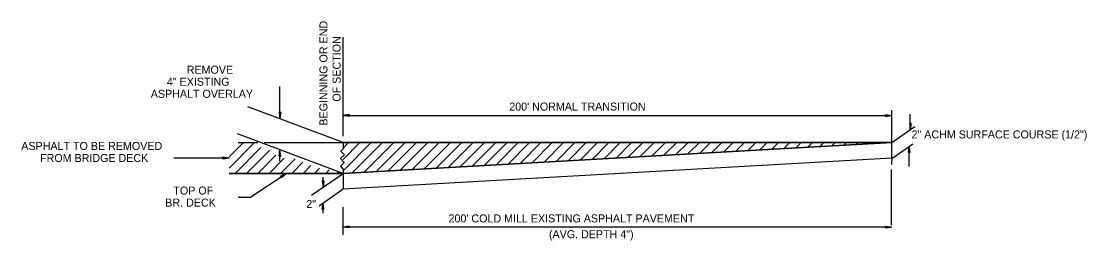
# Model space of a CAD drawing. Extents: x 1929624 to 1936506, y 596315 to 605721.
# Drawn here: x 1935707 to 1936506, y 602708 to 602872 of the extents above; entities that cross this region are included whole.
import ezdxf

# ---------------------------------------------------------------- set-up
doc = ezdxf.new("R2010")
doc.units = 0
doc.layers.add('Default', color=7, linetype='Continuous')
doc.layers.add('R_Border', color=7, linetype='Continuous')

msp = doc.modelspace()

# ---------------------------------------------------------------- linework, layer by layer
at = {"layer": 'Default'}
for p, q in [((1935948.07, 602786.61), (1935948.07, 602860.53)), ((1935900.69, 602799.72), (1935900.69, 602823.71)), ((1935948.07, 602781.78), (1935876.52, 602808.5)), ((1935900.02, 602804.17), (1935900.69, 602799.72)), ((1935900.02, 602804.17), (1935900.69, 602800.38)), ((1935901.35, 602804.17), (1935900.02, 602804.17)), ((1935900.25, 602804.17), (1935900.69, 602801.28)), ((1935900.25, 602804.17), (1935900.69, 602801.93)), ((1935900.47, 602804.17), (1935900.69, 602802.83)), ((1935900.47, 602804.17), (1935900.69, 602803.49)), ((1935901.35, 602804.17), (1935900.69, 602799.72)), ((1935900.9, 602804.17), (1935900.69, 602802.83)), ((1935901.14, 602804.17), (1935900.69, 602801.28)), ((1935901.14, 602804.17), (1935900.69, 602800.38)), ((1935900.9, 602804.17), (1935900.69, 602801.93)), ((1935900.69, 602804.17), (1935900.69, 602803.49)), ((1935952.74, 602802.67), (1935948.07, 602802)), ((1935948.07, 602802), (1936359.63, 602802)), ((1935952.74, 602801.34), (1935948.07, 602802)), ((1935952.74, 602802.45), (1935948.75, 602802)), ((1935952.74, 602801.34), (1935948.75, 602802)), ((1935952.74, 602802.45), (1935949.64, 602802)), ((1935952.74, 602801.56), (1935949.64, 602802)), ((1935952.74, 602802.23), (1935950.53, 602802)), ((1935952.74, 602801.56), (1935950.53, 602802)), ((1935952.74, 602802.23), (1935951.19, 602802)), ((1935952.74, 602801.79), (1935951.19, 602802)), ((1935952.74, 602802), (1935952.08, 602802)), ((1935952.74, 602801.79), (1935952.08, 602802)), ((1935952.74, 602801.34), (1935952.74, 602802.67)), ((1936354.96, 602802.67), (1936359.63, 602802)), ((1936354.96, 602802.67), (1936354.96, 602801.34)), ((1936354.96, 602802.45), (1936358.08, 602802)), ((1936354.96, 602802.45), (1936358.72, 602802)), ((1936354.96, 602802.23), (1936356.51, 602802)), ((1936354.96, 602802.23), (1936357.19, 602802)), ((1936354.96, 602801.34), (1936359.63, 602802)), ((1936354.96, 602801.79), (1936356.51, 602802)), ((1936354.96, 602801.56), (1936358.08, 602802)), ((1936354.96, 602801.34), (1936358.72, 602802)), ((1936354.96, 602801.56), (1936357.19, 602802)), ((1936354.96, 602801.79), (1936355.63, 602802)), ((1936354.96, 602802), (1936355.63, 602802)), ((1936359.63, 602781.78), (1936359.63, 602805.99)), ((1936373.39, 602791.32), (1936373.39, 602803.09)), ((1936359.63, 602781.78), (1936376.95, 602793.77)), ((1936372.73, 602795.98), (1936373.39, 602791.32)), ((1936374.06, 602795.98), (1936372.73, 602795.98)), ((1936372.96, 602795.98), (1936373.39, 602792.88)), ((1936372.96, 602795.98), (1936373.39, 602792.21)), ((1936373.17, 602795.98), (1936373.39, 602794.44)), ((1936373.17, 602795.98), (1936373.39, 602793.77)), ((1936374.06, 602795.98), (1936373.39, 602791.32)), ((1936373.61, 602795.98), (1936373.39, 602794.44)), ((1936373.85, 602795.98), (1936373.39, 602792.88)), ((1936374.06, 602795.98), (1936373.39, 602792.21)), ((1936373.85, 602795.98), (1936373.39, 602793.77)), ((1936373.39, 602795.98), (1936373.39, 602795.32)), ((1936373.61, 602795.98), (1936373.39, 602795.32)), ((1935948.01, 602758.7), (1935868.93, 602788.16)), ((1935862.62, 602762.68), (1935881.73, 602781.78)), ((1935862.62, 602771.16), (1935873.25, 602781.78)), ((1935867.14, 602758.7), (1935886.47, 602778.03)), ((1935869.44, 602781.78), (1935884.08, 602781.78)), ((1935888.85, 602781.78), (1935898.31, 602781.78)), ((1935898.31, 602781.78), (1936359.63, 602781.78)), ((1935948.07, 602777.66), (1935952.19, 602781.78)), ((1935948.08, 602769.19), (1935960.68, 602781.78)), ((1935948.09, 602760.71), (1935969.17, 602781.78)), ((1935954.96, 602759.09), (1935977.65, 602781.78)), ((1935963.95, 602759.6), (1935986.14, 602781.78)), ((1935972.94, 602760.1), (1935994.62, 602781.78)), ((1935981.93, 602760.61), (1936003.11, 602781.78)), ((1935990.92, 602761.11), (1936011.59, 602781.78)), ((1935999.91, 602761.61), (1936020.08, 602781.78)), ((1936008.9, 602762.12), (1936028.56, 602781.78)), ((1936017.89, 602762.62), (1936037.05, 602781.78)), ((1936026.87, 602763.13), (1936045.53, 602781.78)), ((1936035.86, 602763.63), (1936054.02, 602781.78)), ((1936044.85, 602764.13), (1936062.5, 602781.78)), ((1936053.84, 602764.64), (1936070.99, 602781.78)), ((1936062.83, 602765.14), (1936079.47, 602781.78)), ((1936071.82, 602765.65), (1936087.96, 602781.78)), ((1936080.81, 602766.15), (1936096.44, 602781.78)), ((1936089.8, 602766.65), (1936104.93, 602781.78)), ((1936098.79, 602767.16), (1936113.41, 602781.78)), ((1936107.78, 602767.66), (1936121.9, 602781.78)), ((1936116.77, 602768.17), (1936130.39, 602781.78)), ((1936125.76, 602768.67), (1936138.87, 602781.78)), ((1936134.75, 602769.17), (1936147.36, 602781.78)), ((1936143.74, 602769.68), (1936155.84, 602781.78)), ((1936152.73, 602770.18), (1936164.33, 602781.78)), ((1936161.71, 602770.69), (1936172.81, 602781.78)), ((1936170.7, 602771.19), (1936181.3, 602781.78)), ((1936179.69, 602771.69), (1936189.78, 602781.78)), ((1936188.68, 602772.2), (1936198.27, 602781.78)), ((1936197.67, 602772.7), (1936206.75, 602781.78)), ((1936206.66, 602773.21), (1936215.24, 602781.78)), ((1936215.65, 602773.71), (1936223.72, 602781.78)), ((1936224.64, 602774.21), (1936232.21, 602781.78)), ((1936233.63, 602774.72), (1936240.69, 602781.78)), ((1936242.62, 602775.22), (1936249.18, 602781.78)), ((1936251.61, 602775.73), (1936257.66, 602781.78)), ((1936260.6, 602776.23), (1936266.15, 602781.78)), ((1936269.59, 602776.73), (1936274.64, 602781.78)), ((1936278.58, 602777.24), (1936283.12, 602781.78)), ((1936287.56, 602777.74), (1936291.61, 602781.78)), ((1936296.55, 602778.25), (1936300.09, 602781.78)), ((1936305.54, 602778.75), (1936308.58, 602781.78)), ((1936314.53, 602779.26), (1936317.06, 602781.78)), ((1936323.52, 602779.76), (1936325.55, 602781.78)), ((1936332.51, 602780.26), (1936334.03, 602781.78)), ((1936341.5, 602780.77), (1936342.52, 602781.78)), ((1936350.49, 602781.27), (1936351, 602781.78)), ((1936359.48, 602781.78), (1936359.49, 602781.78)), ((1936359.63, 602770.25), (1936359.63, 602781.78)), ((1936360.28, 602770.26), (1936375.38, 602780.91)), ((1936372.05, 602774.26), (1936372.71, 602778.93)), ((1936372.28, 602774.26), (1936372.71, 602778.26)), ((1936372.28, 602774.26), (1936372.71, 602777.36)), ((1936372.48, 602774.26), (1936372.71, 602776.7)), ((1936372.71, 602763.82), (1936372.71, 602778.93)), ((1936373.38, 602774.26), (1936372.71, 602778.93)), ((1936373.38, 602774.26), (1936372.71, 602778.26)), ((1936373.16, 602774.26), (1936372.71, 602777.36)), ((1936373.16, 602774.26), (1936372.71, 602776.7)), ((1935821.06, 602770.24), (1935862.62, 602770.24)), ((1935857.91, 602769.54), (1935857.96, 602770.95)), ((1935857.91, 602769.54), (1935862.62, 602770.24)), ((1935857.92, 602770.65), (1935861.03, 602770.18)), ((1935857.96, 602770.95), (1935862.62, 602770.24)), ((1935857.96, 602769.85), (1935859.61, 602770.23)), ((1935857.96, 602769.85), (1935860.21, 602770.13)), ((1935858.01, 602770.15), (1935858.8, 602770.2)), ((1935858.01, 602770.15), (1935858.8, 602770.2)), ((1935858.05, 602770.46), (1935859.61, 602770.23)), ((1935858.05, 602770.46), (1935860.21, 602770.13)), ((1935858.09, 602770.77), (1935861.83, 602770.21)), ((1935858.09, 602769.67), (1935861.83, 602770.21)), ((1935858.09, 602769.67), (1935861.03, 602770.18)), ((1935875.62, 602758.7), (1935893.08, 602776.16)), ((1935884.11, 602758.7), (1935897.72, 602772.31)), ((1935892.59, 602758.7), (1935903.96, 602770.07)), ((1935900.02, 602771.63), (1935900.69, 602776.29)), ((1935900.02, 602771.63), (1935900.69, 602775.63)), ((1935900.02, 602771.63), (1935901.35, 602771.63)), ((1935900.25, 602771.63), (1935900.69, 602774.74)), ((1935900.25, 602771.63), (1935900.69, 602774.09)), ((1935900.47, 602771.63), (1935900.69, 602773.19)), ((1935900.47, 602771.63), (1935900.69, 602772.29)), ((1935901.35, 602771.63), (1935900.69, 602776.29)), ((1935900.69, 602767.86), (1935900.69, 602776.29)), ((1935901.14, 602771.63), (1935900.69, 602775.63)), ((1935901.14, 602771.63), (1935900.69, 602774.74)), ((1935900.9, 602771.63), (1935900.69, 602774.09)), ((1935900.9, 602771.63), (1935900.69, 602773.19)), ((1935900.69, 602771.63), (1935900.69, 602772.29)), ((1935901.08, 602758.7), (1935912.01, 602769.64)), ((1935948.07, 602747.15), (1936359.63, 602770.25)), ((1936359.63, 602770.25), (1936359.43, 602765.28)), ((1936372.05, 602774.26), (1936373.38, 602774.26)), ((1936372.48, 602774.26), (1936372.71, 602775.8)), ((1936372.93, 602774.26), (1936372.71, 602775.8)), ((1936372.93, 602774.26), (1936372.71, 602775.15)), ((1936372.71, 602774.26), (1936372.71, 602775.15)), ((1935909.56, 602758.7), (1935917.88, 602767.02)), ((1935918.05, 602758.7), (1935923.9, 602764.56)), ((1935926.53, 602758.7), (1935930.43, 602762.6)), ((1935935.02, 602758.7), (1935937.68, 602761.37)), ((1936359.4, 602719.93), (1936359.4, 602761.57)), ((1935862.62, 602758.7), (1935948.01, 602758.7)), ((1935878.11, 602740.59), (1935905.32, 602758.7)), ((1935901.05, 602756.71), (1935905.32, 602758.7)), ((1935901.78, 602755.5), (1935901.05, 602756.71)), ((1935901.18, 602756.43), (1935904.02, 602757.76)), ((1935901.25, 602756.63), (1935904.67, 602758.24)), ((1935901.39, 602756.35), (1935903.37, 602757.28)), ((1935901.39, 602756.35), (1935902.82, 602757.02)), ((1935901.53, 602756.07), (1935902.16, 602756.54)), ((1935901.53, 602756.07), (1935902.16, 602756.54)), ((1935901.66, 602755.79), (1935903.37, 602757.28)), ((1935901.66, 602755.79), (1935902.82, 602757.02)), ((1935901.78, 602755.5), (1935905.32, 602758.7)), ((1935901.86, 602755.72), (1935904.67, 602758.24)), ((1935901.86, 602755.72), (1935904.02, 602757.76)), ((1935924.46, 602742.4), (1935948.01, 602758.7)), ((1935932.4, 602752.99), (1935933.06, 602748.32)), ((1935933.73, 602752.99), (1935932.4, 602752.99)), ((1935932.63, 602752.99), (1935933.06, 602749.88)), ((1935932.63, 602752.99), (1935933.06, 602749.22)), ((1935932.84, 602752.99), (1935933.06, 602751.44)), ((1935932.84, 602752.99), (1935933.06, 602750.77)), ((1935933.06, 602748.32), (1935933.06, 602755.9)), ((1935933.73, 602752.99), (1935933.06, 602748.32)), ((1935933.28, 602752.99), (1935933.06, 602751.44)), ((1935933.52, 602752.99), (1935933.06, 602749.88)), ((1935933.73, 602752.99), (1935933.06, 602749.22)), ((1935933.52, 602752.99), (1935933.06, 602750.77)), ((1935933.06, 602752.99), (1935933.06, 602752.32)), ((1935933.28, 602752.99), (1935933.06, 602752.32)), ((1935943.5, 602758.7), (1935944.73, 602759.93)), ((1935930.03, 602734.49), (1935948.01, 602747.16)), ((1935878.17, 602740.51), (1935869.4, 602740.51)), ((1935932.39, 602731.86), (1935933.05, 602736.53)), ((1935933.71, 602731.86), (1935933.05, 602736.53)), ((1935933.05, 602728.98), (1935933.05, 602736.53)), ((1935932.39, 602731.86), (1935933.71, 602731.86)), ((1935932.61, 602731.86), (1935933.05, 602735.86)), ((1935932.61, 602731.86), (1935933.05, 602734.97)), ((1935932.82, 602731.86), (1935933.05, 602734.3)), ((1935932.82, 602731.86), (1935933.05, 602733.41)), ((1935933.71, 602731.86), (1935933.05, 602735.86)), ((1935933.5, 602731.86), (1935933.05, 602734.97)), ((1935933.5, 602731.86), (1935933.05, 602734.3)), ((1935933.27, 602731.86), (1935933.05, 602733.41)), ((1935933.27, 602731.86), (1935933.05, 602732.76)), ((1935933.05, 602731.86), (1935933.05, 602732.76)), ((1935948.07, 602712.68), (1935948.07, 602733.48)), ((1935952.53, 602719.17), (1935948.07, 602718.51)), ((1936359.4, 602718.51), (1935948.07, 602718.51)), ((1935952.53, 602717.84), (1935948.07, 602718.51)), ((1935952.53, 602719.17), (1935948.75, 602718.51)), ((1935952.53, 602718.06), (1935948.75, 602718.51)), ((1935952.53, 602718.96), (1935949.64, 602718.51)), ((1935952.53, 602718.06), (1935949.64, 602718.51)), ((1935952.53, 602718.96), (1935950.3, 602718.51)), ((1935952.53, 602718.29), (1935950.3, 602718.51)), ((1935952.53, 602718.72), (1935951.19, 602718.51)), ((1935952.53, 602718.29), (1935951.19, 602718.51)), ((1935952.53, 602718.72), (1935951.86, 602718.51)), ((1935952.53, 602718.51), (1935951.86, 602718.51)), ((1935952.53, 602717.84), (1935952.53, 602719.17)), ((1936354.96, 602719.17), (1936359.4, 602718.51)), ((1936354.96, 602719.17), (1936358.72, 602718.51)), ((1936354.96, 602719.17), (1936354.96, 602717.84)), ((1936354.96, 602718.96), (1936357.84, 602718.51)), ((1936354.96, 602718.96), (1936357.19, 602718.51)), ((1936354.96, 602718.72), (1936356.3, 602718.51)), ((1936354.96, 602718.72), (1936355.63, 602718.51)), ((1936354.96, 602717.84), (1936359.4, 602718.51)), ((1936354.96, 602718.29), (1936356.3, 602718.51)), ((1936354.96, 602718.06), (1936357.84, 602718.51)), ((1936354.96, 602718.06), (1936358.72, 602718.51)), ((1936354.96, 602718.29), (1936357.19, 602718.51)), ((1936354.96, 602718.51), (1936355.63, 602718.51))]:
    msp.add_line(p, q, dxfattribs=at)
for points in [[(1935948.06, 602778.9), (1935948.06, 602777.15), (1935946.26, 602775.41), (1935949.04, 602772.53), (1935946.16, 602769.76), (1935948.93, 602766.88), (1935946.05, 602764.1), (1935948.02, 602761.59)], [(1935948.02, 602761.59), (1935948.01, 602758.7), (1936359.63, 602781.78), (1935948.07, 602781.78)], [(1935948.01, 602758.7), (1935948.07, 602747.15), (1936359.63, 602770.25), (1936359.63, 602781.78), (1935948.01, 602758.7)], [(1935948.01, 602758.7), (1935948.07, 602747.15), (1936359.63, 602770.25), (1936359.63, 602781.78), (1935948.01, 602758.7)], [(1935948.07, 602781.78), (1935948.06, 602778.9)], [(1935948.01, 602758.7), (1935862.62, 602758.7), (1935862.62, 602758.7)]]:
    msp.add_lwpolyline(points, dxfattribs=at)
at = {"layer": 'R_Border'}
msp.add_line((1935948.01, 602758.7), (1936359.63, 602781.78), dxfattribs=at)

# ---------------------------------------------------------------- texts
at = {"layer": 'Default'}
for s, rotation, p in [('BEGINNING OR END', 90, (1935936.34, 602794.4)), ('OF SECTION', 90, (1935946.2, 602812.34)), ('REMOVE', 360, (1935830.79, 602833.25)), ('4" EXISTING ', 360, (1935815.91, 602824.25)), ('ASPHALT OVERLAY', 360, (1935803.82, 602815.25)), ("200' NORMAL TRANSITION ", 360, (1936072.67, 602805.7)), ('2" ACHM SURFACE COURSE (1/2")', 360, (1936374.36, 602784.85)), ('ASPHALT TO BE REMOVED', 360, (1935706.72, 602776.21)), (' FROM BRIDGE DECK', 360, (1935718.59, 602767.21)), ('TOP OF ', 360, (1935820.78, 602742.81)), ('BR. DECK', 360, (1935814.69, 602733.81)), ('2"', 360, (1935920.47, 602732.76)), ("200' COLD MILL EXISTING ASPHALT PAVEMENT", 360, (1936027.14, 602721.98)), ('(AVG. DEPTH 4")', 360, (1936102.46, 602710.14))]:
    msp.add_text(s, height=6, rotation=rotation, dxfattribs=at).set_placement(p)

doc.saveas('drawing.dxf')
